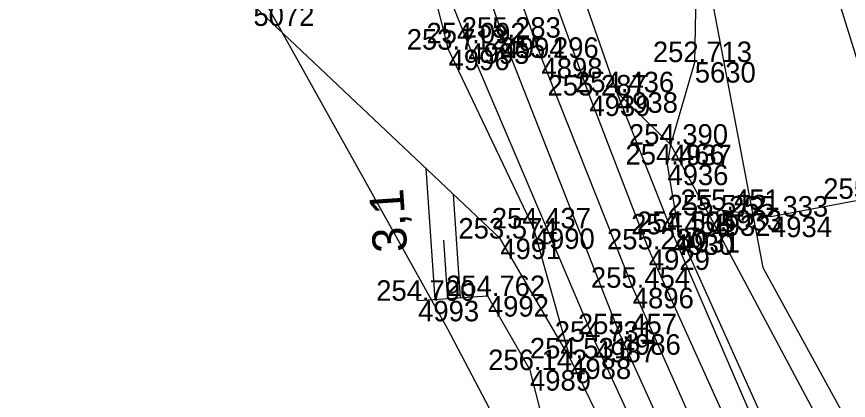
# Model space of a CAD drawing. Extents: x -809970 to -809480, y -1011362 to -1010672.
# Drawn here: x -809861.49 to -809812.83, y -1011032.69 to -1011010.25 of the extents above; entities that cross this region are included whole.
import ezdxf

# ---------------------------------------------------------------- set-up
doc = ezdxf.new("R2010")
doc.units = 0
for name, color, linetype in [('Vrstva 1', 7, 'Continuous'), ('Vrstva 4', 7, 'Continuous'), ('Vrstva 48', 7, 'Continuous'), ('Vrstva 49', 7, 'Continuous'), ('Vrstva 53', 7, 'Continuous'), ('Vrstva 60', 7, 'Continuous'), ('Vrstva 61', 7, 'Continuous')]:
    doc.layers.add(name, color=color, linetype=linetype)

msp = doc.modelspace()

# ---------------------------------------------------------------- linework, layer by layer
at = {"layer": 'Vrstva 1'}
msp.add_lwpolyline([(-809820.002, -1011038.37), (-809825.442, -1011026.104), (-809830.785, -1011012.658), (-809834.485, -1011002.308), (-809836.415, -1010996.462), (-809838.541, -1010989.632), (-809841.189, -1010980.417), (-809842.723, -1010974.633), (-809843.612, -1010971.08), (-809845.723, -1010962.088), (-809847.264, -1010954.929), (-809848.141, -1010950.637), (-809848.896, -1010946.737), (-809850.898, -1010935.751), (-809852.809, -1010924.513), (-809856.326, -1010902.237), (-809858.786, -1010885.982), (-809860.306, -1010875.864), (-809863.238, -1010856.222), (-809865.824, -1010838.832), (-809869.271, -1010815.693)], dxfattribs=at)
at = {"layer": 'Vrstva 4'}
for points in [[(-809821.494, -1011039.157), (-809826.205, -1011028.819), (-809833.001, -1011011.481), (-809837.78, -1010997.54), (-809838.806, -1010997.207), (-809843.283, -1010980.934), (-809843.041, -1010980.213), (-809846.285, -1010966.658), (-809849.289, -1010953.139), (-809852.706, -1010936.051), (-809854.789, -1010922.512), (-809857.871, -1010903.005), (-809861.561, -1010877.867), (-809862.279, -1010876.008), (-809867.764, -1010839.12), (-809867.776, -1010837.677), (-809868.98, -1010830.232), (-809873.561, -1010797.792), (-809876.118, -1010779.988), (-809878.6, -1010761.673), (-809881.093, -1010740.742), (-809883.606, -1010712.064)], [(-809818.366, -1011037.45), (-809824.503, -1011023.859), (-809827.98, -1011014.861), (-809832.548, -1011002.245), (-809834.342, -1010996.578), (-809834.105, -1010995.845), (-809838.678, -1010979.669), (-809839.533, -1010979.34), (-809840.375, -1010976.742), (-809844.107, -1010961.611), (-809846.272, -1010950.024), (-809849.263, -1010935.563), (-809851.188, -1010924.288), (-809854.685, -1010902.149), (-809857.441, -1010883.897), (-809858.703, -1010875.93), (-809858.211, -1010875.546), (-809863.759, -1010838.589), (-809864.243, -1010838.113), (-809864.684, -1010833.803), (-809870.275, -1010797.222)], [(-809817.164, -1011036.691), (-809823.084, -1011022.979), (-809826.372, -1011014.673), (-809832.993, -1010995.743), (-809834.017, -1010995.842), (-809834.085, -1010995.877), (-809834.105, -1010995.845)], [(-809822.783, -1011039.81), (-809827.652, -1011029.26), (-809835.066, -1011011.811), (-809838.453, -1011003.356), (-809838.896, -1010997.269), (-809838.806, -1010997.207)]]:
    msp.add_lwpolyline(points, dxfattribs=at)
at = {"layer": 'Vrstva 48'}
for p, q in [((-809809.99, -1011020.331), (-809818.307, -1010993.324)), ((-809837.014, -1011026.798), (-809837.528, -1011019.135)), ((-809835.517, -1011026.697), (-809835.923, -1011020.65)), ((-809836.265, -1011026.747), (-809836.495, -1011023.32))]:
    msp.add_line(p, q, dxfattribs=at)
at = {"layer": 'Vrstva 49'}
for points in [[(-809823.22, -1011017.736), (-809821.817, -1011012.906), (-809821.728, -1011008.905), (-809824.518, -1010995.159), (-809832.993, -1010995.743)], [(-809820.959, -1011021.87), (-809823.22, -1011017.736), (-809826.372, -1011014.673), (-809832.993, -1010995.743)], [(-809824.251, -1011040.285), (-809829.107, -1011030.235), (-809833.194, -1011023.226), (-809847.638, -1011009.591), (-809850.438, -1011005.143), (-809847.756, -1011001.46), (-809847.53, -1011001.971), (-809839.895, -1010997.835), (-809838.896, -1010997.269)], [(-809829.107, -1011030.235), (-809831.239, -1011022.633), (-809836.221, -1011012.179), (-809838.453, -1011003.356), (-809838.896, -1010997.269)], [(-809814.251, -1011034.457), (-809820.959, -1011021.87), (-809820.291, -1011021.554), (-809817.36, -1011021.943), (-809811.853, -1011020.905), (-809803.209, -1011018.243), (-809793.842, -1011014.816)], [(-809816.632, -1011036.445), (-809822.747, -1011022.841), (-809823.419, -1011018.902), (-809823.22, -1011017.736)], [(-809829.173, -1011039.904), (-809831.457, -1011030.917), (-809833.92, -1011026.59), (-809838.003, -1011026.864)]]:
    msp.add_lwpolyline(points, dxfattribs=at)
at = {"layer": 'Vrstva 53'}
for points in [[(-809810.89, -1011076.81), (-809836.26, -1011028.53), (-809850.32, -1011003.33), (-809854.51, -1011000.24), (-809856.34, -1010998.68), (-809859.52, -1010995.97), (-809864.77, -1010992.44), (-809865.72, -1010986.44), (-809870.58, -1010955.65), (-809883.99, -1010901.78), (-809890.33, -1010872.36), (-809892.39, -1010868.68), (-809893.92, -1010865.41), (-809894.78, -1010861.65), (-809898.21, -1010828.41), (-809898.47, -1010814.6), (-809887.66, -1010796.86), (-809893.8, -1010725.05), (-809890.92, -1010677.02)], [(-809848.47, -1010824.63), (-809848.99, -1010834.52), (-809828.94, -1010831.94), (-809811.76, -1010846.11), (-809806.99, -1010849.89), (-809798.33, -1010856.76), (-809803.49, -1010861.61), (-809820.27, -1010877.38), (-809819.54, -1010907.65), (-809817.34, -1010954.54), (-809819.55, -1010971.19), (-809826.87, -1010981.55), (-809825.08, -1010988.69), (-809823.59, -1010994.66), (-809817.83, -1011024.91), (-809805.06, -1011048.21)]]:
    msp.add_lwpolyline(points, dxfattribs=at)
at = {"layer": 'Vrstva 60'}
for p, q in [((-809833.001, -1011011.481), (-809833.001, -1011011.481)), ((-809835.066, -1011011.811), (-809835.066, -1011011.811)), ((-809836.221, -1011012.179), (-809836.221, -1011012.179)), ((-809830.785, -1011012.658), (-809830.785, -1011012.658)), ((-809821.817, -1011012.906), (-809821.817, -1011012.906)), ((-809827.98, -1011014.861), (-809827.98, -1011014.861)), ((-809826.372, -1011014.673), (-809826.372, -1011014.673)), ((-809823.22, -1011017.736), (-809823.22, -1011017.736)), ((-809823.419, -1011018.902), (-809823.419, -1011018.902)), ((-809820.291, -1011021.554), (-809820.291, -1011021.554)), ((-809820.959, -1011021.87), (-809820.959, -1011021.87)), ((-809817.36, -1011021.943), (-809817.36, -1011021.943)), ((-809831.239, -1011022.633), (-809831.239, -1011022.633)), ((-809823.084, -1011022.979), (-809823.084, -1011022.979)), ((-809822.747, -1011022.841), (-809822.747, -1011022.841)), ((-809833.194, -1011023.226), (-809833.194, -1011023.226)), ((-809824.503, -1011023.859), (-809824.503, -1011023.859)), ((-809825.442, -1011026.104), (-809825.442, -1011026.104)), ((-809833.92, -1011026.59), (-809833.92, -1011026.59)), ((-809838.003, -1011026.864), (-809838.003, -1011026.864)), ((-809826.205, -1011028.819), (-809826.205, -1011028.819)), ((-809827.652, -1011029.26), (-809827.652, -1011029.26)), ((-809829.107, -1011030.235), (-809829.107, -1011030.235)), ((-809831.457, -1011030.917), (-809831.457, -1011030.917))]:
    msp.add_line(p, q, dxfattribs=at)

# ---------------------------------------------------------------- texts
at = {"layer": 'Vrstva 48'}
msp.add_text('3,1', height=2, rotation=93.8392, dxfattribs=at).set_placement((-809838.633, -1011023.97))
at = {"layer": 'Vrstva 60'}
for s, p in [('5072', (-809847.638, -1011010.791)), ('4994', (-809833.001, -1011012.681)), ('4995', (-809835.066, -1011013.011)), ('4996', (-809836.221, -1011013.379)), ('4898', (-809830.785, -1011013.858)), ('5630', (-809821.817, -1011014.106)), ('4939', (-809827.98, -1011016.061)), ('4938', (-809826.372, -1011015.873)), ('4937', (-809823.22, -1011018.936)), ('4936', (-809823.419, -1011020.102)), ('4933', (-809820.291, -1011022.754)), ('4932', (-809820.959, -1011023.07)), ('4934', (-809817.36, -1011023.143)), ('4990', (-809831.239, -1011023.833)), ('4930', (-809823.084, -1011024.179)), ('4931', (-809822.747, -1011024.041)), ('4991', (-809833.194, -1011024.426)), ('4929', (-809824.503, -1011025.059)), ('4896', (-809825.442, -1011027.304)), ('4992', (-809833.92, -1011027.79)), ('4993', (-809838.003, -1011028.064)), ('4986', (-809826.205, -1011030.019)), ('4987', (-809827.652, -1011030.46)), ('4988', (-809829.107, -1011031.435)), ('4989', (-809831.457, -1011032.117))]:
    msp.add_text(s, height=1.2, dxfattribs=at).set_placement(p)
at = {"layer": 'Vrstva 61'}
for s, p in [('255.283', (-809835.453, -1011011.481)), ('253.712', (-809838.669, -1011012.179)), ('254.092', (-809837.514, -1011011.811)), ('255.296', (-809833.237, -1011012.658)), ('252.713', (-809824.269, -1011012.906)), ('254.436', (-809828.824, -1011014.673)), ('255.287', (-809830.432, -1011014.861)), ('254.390', (-809825.671, -1011017.736)), ('254.466', (-809825.871, -1011018.902)), ('255.494', (-809814.304, -1011020.905)), ('255.572', (-809823.407, -1011021.87)), ('255.451', (-809822.648, -1011021.554)), ('255.333', (-809819.812, -1011021.943)), ('254.437', (-809833.691, -1011022.633)), ('254.505', (-809825.203, -1011022.841)), ('253.574', (-809835.645, -1011023.226)), ('254.458', (-809825.538, -1011022.979)), ('255.280', (-809826.954, -1011023.859)), ('255.454', (-809827.893, -1011026.104)), ('254.762', (-809836.368, -1011026.59)), ('254.790', (-809840.454, -1011026.864)), ('254.731', (-809830.009, -1011029.26)), ('255.457', (-809828.657, -1011028.819)), ('254.531', (-809831.464, -1011030.235)), ('256.142', (-809833.905, -1011030.917))]:
    msp.add_text(s, height=1.2, dxfattribs=at).set_placement(p)

doc.saveas('drawing.dxf')
